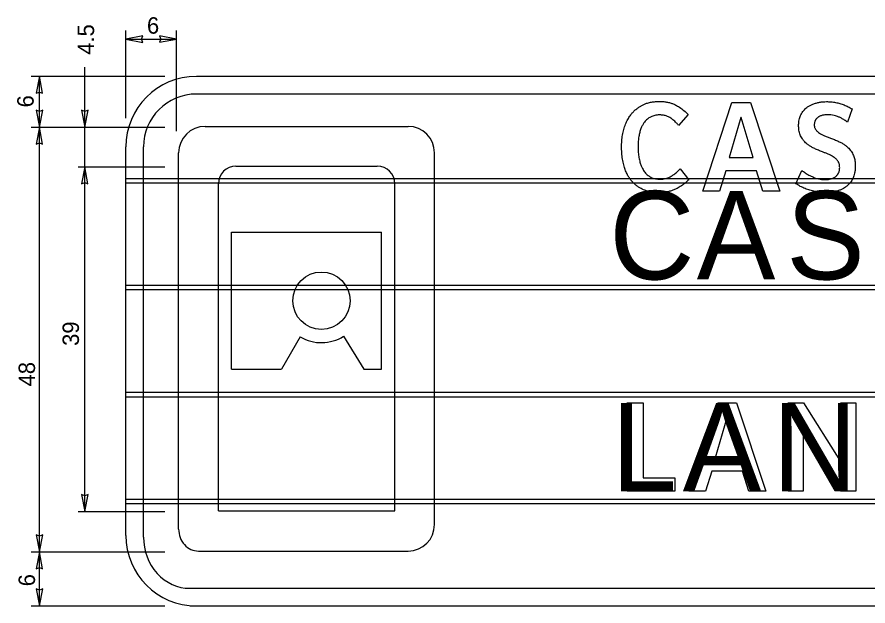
# Model space of a CAD drawing. Extents: x 319706 to 320449, y 1621775 to 1622117.
# Drawn here: x 320308.6 to 320381.2, y 1621854.2 to 1621904.4 of the extents above; entities that cross this region are included whole.
import ezdxf

# ---------------------------------------------------------------- set-up
doc = ezdxf.new("R2010")
doc.units = 0
for name, color, linetype in [('1', 7, 'Continuous'), ('52', 7, 'Continuous'), ('GSBWFill', 7, 'Continuous'), ('GSColorFill', 7, 'Continuous'), ('GSOutline', 7, 'Continuous'), ('SignPanel', 7, 'Continuous')]:
    doc.layers.add(name, color=color, linetype=linetype)

msp = doc.modelspace()

# ---------------------------------------------------------------- linework, layer by layer
at = {"layer": '1'}
for p, q in [((320317.921, 1621895.788), (320317.921, 1621903.248)), ((320322.25, 1621894.663), (320322.25, 1621903.248)), ((320317.921, 1621902.519), (320322.25, 1621902.519)), ((320314.417, 1621895.01), (320314.417, 1621900.114)), ((320309.855, 1621899.343), (320321.239, 1621899.343)), ((320310.552, 1621895.01), (320310.552, 1621899.343)), ((320309.855, 1621895.01), (320321.239, 1621895.01)), ((320310.552, 1621858.786), (320310.552, 1621895.01)), ((320314.417, 1621891.622), (320314.417, 1621895.01)), ((320313.858, 1621891.622), (320321.239, 1621891.622)), ((320314.417, 1621862.212), (320314.417, 1621891.622)), ((320313.858, 1621862.212), (320321.239, 1621862.212)), ((320309.855, 1621858.786), (320321.239, 1621858.786)), ((320310.552, 1621854.168), (320310.552, 1621858.786)), ((320309.855, 1621854.168), (320321.239, 1621854.168))]:
    msp.add_line(p, q, dxfattribs=at)
at = {"layer": '52'}
for p, q in [((320319.371, 1621902.789), (320317.921, 1621902.519)), ((320317.921, 1621902.519), (320319.371, 1621902.239)), ((320319.261, 1621902.519), (320319.371, 1621902.789)), ((320319.371, 1621902.239), (320319.261, 1621902.519)), ((320322.25, 1621902.519), (320320.8, 1621902.799)), ((320320.8, 1621902.799), (320320.91, 1621902.519)), ((320320.91, 1621902.519), (320320.8, 1621902.249)), ((320320.8, 1621902.249), (320322.25, 1621902.519)), ((320310.552, 1621899.343), (320310.272, 1621897.893)), ((320310.822, 1621897.893), (320310.552, 1621899.343)), ((320310.272, 1621897.893), (320310.552, 1621898.003)), ((320310.552, 1621898.003), (320310.822, 1621897.893)), ((320310.552, 1621896.35), (320310.282, 1621896.46)), ((320310.282, 1621896.46), (320310.552, 1621895.01)), ((320310.552, 1621895.01), (320310.832, 1621896.46)), ((320310.832, 1621896.46), (320310.552, 1621896.35)), ((320314.417, 1621896.35), (320314.147, 1621896.46)), ((320314.147, 1621896.46), (320314.417, 1621895.01)), ((320314.417, 1621895.01), (320314.697, 1621896.46)), ((320314.697, 1621896.46), (320314.417, 1621896.35)), ((320310.552, 1621895.01), (320310.272, 1621893.56)), ((320310.822, 1621893.56), (320310.552, 1621895.01)), ((320310.272, 1621893.56), (320310.552, 1621893.67)), ((320310.552, 1621893.67), (320310.822, 1621893.56)), ((320314.417, 1621891.622), (320314.137, 1621890.172)), ((320314.687, 1621890.172), (320314.417, 1621891.622)), ((320314.137, 1621890.172), (320314.417, 1621890.282)), ((320314.417, 1621890.282), (320314.687, 1621890.172)), ((320314.417, 1621863.552), (320314.147, 1621863.662)), ((320314.147, 1621863.662), (320314.417, 1621862.212)), ((320314.417, 1621862.212), (320314.697, 1621863.662)), ((320314.697, 1621863.662), (320314.417, 1621863.552)), ((320310.552, 1621860.126), (320310.282, 1621860.236)), ((320310.282, 1621860.236), (320310.552, 1621858.786)), ((320310.552, 1621858.786), (320310.832, 1621860.236)), ((320310.832, 1621860.236), (320310.552, 1621860.126)), ((320310.552, 1621858.786), (320310.272, 1621857.336)), ((320310.822, 1621857.336), (320310.552, 1621858.786)), ((320310.272, 1621857.336), (320310.552, 1621857.446)), ((320310.552, 1621857.446), (320310.822, 1621857.336)), ((320310.552, 1621855.508), (320310.282, 1621855.618)), ((320310.282, 1621855.618), (320310.552, 1621854.168)), ((320310.552, 1621854.168), (320310.832, 1621855.618)), ((320310.832, 1621855.618), (320310.552, 1621855.508))]:
    msp.add_line(p, q, dxfattribs=at)
at = {"layer": 'GSOutline'}
for points in [[(320372.274, 1621889.554), (320371.724, 1621891.274), (320369.121, 1621891.274), (320368.571, 1621889.554), (320367.157, 1621889.554), (320369.625, 1621897.102), (320371.213, 1621897.102), (320373.733, 1621889.554), (320372.274, 1621889.554)], [(320379.889, 1621896.575), (320379.49, 1621895.438)], [(320365.893, 1621896.095), (320365.088, 1621895.162)], [(320370.437, 1621895.821), (320370.4, 1621895.823), (320369.392, 1621892.409), (320371.446, 1621892.409), (320370.437, 1621895.821)], [(320365.225, 1621891.465), (320365.947, 1621890.525)], [(320375.093, 1621890.183), (320375.605, 1621891.312)], [(320360.7, 1621863.954), (320360.7, 1621871.484), (320362.054, 1621871.484), (320362.054, 1621865.107), (320364.753, 1621865.107), (320364.753, 1621863.954), (320360.7, 1621863.954)], [(320371.082, 1621863.954), (320370.532, 1621865.674), (320367.929, 1621865.674), (320367.379, 1621863.954), (320365.965, 1621863.954), (320368.433, 1621871.502), (320370.02, 1621871.502), (320372.541, 1621863.954), (320371.082, 1621863.954)], [(320378.919, 1621863.954), (320375.735, 1621868.999), (320375.717, 1621868.999), (320375.717, 1621863.954), (320374.427, 1621863.954), (320374.427, 1621871.484), (320375.735, 1621871.484), (320378.9, 1621866.491), (320378.917, 1621866.491), (320378.919, 1621871.484), (320380.218, 1621871.484), (320380.218, 1621863.954), (320378.919, 1621863.954)], [(320369.245, 1621870.221), (320369.208, 1621870.223), (320368.199, 1621866.809), (320370.254, 1621866.809), (320369.245, 1621870.221)]]:
    msp.add_lwpolyline(points, dxfattribs=at)
for points in [[(320360.22, 1621893.333), (320360.223, 1621893.462), (320360.229, 1621893.84), (320360.295, 1621894.338), (320360.407, 1621894.815), (320360.548, 1621895.261), (320360.745, 1621895.677), (320360.963, 1621896.004), (320361.133, 1621896.22), (320361.321, 1621896.419), (320361.574, 1621896.632), (320361.806, 1621896.784), (320362.003, 1621896.892), (320362.213, 1621896.991), (320362.497, 1621897.09), (320362.862, 1621897.167), (320363.186, 1621897.199), (320363.386, 1621897.202), (320363.455, 1621897.203)], [(320363.455, 1621897.203), (320363.516, 1621897.202), (320363.693, 1621897.2), (320363.981, 1621897.171), (320364.312, 1621897.103), (320364.572, 1621897.016), (320364.819, 1621896.907), (320365.166, 1621896.717), (320365.544, 1621896.435), (320365.802, 1621896.184), (320365.893, 1621896.095)], [(320375.326, 1621895.143), (320375.327, 1621895.188), (320375.328, 1621895.316), (320375.349, 1621895.524), (320375.398, 1621895.757), (320375.461, 1621895.937), (320375.524, 1621896.07), (320375.593, 1621896.194), (320375.69, 1621896.34), (320375.825, 1621896.5), (320375.951, 1621896.618), (320376.087, 1621896.725), (320376.292, 1621896.861), (320376.55, 1621896.984), (320376.825, 1621897.071), (320377.114, 1621897.138), (320377.412, 1621897.179), (320377.637, 1621897.183), (320377.713, 1621897.185)], [(320377.713, 1621897.185), (320377.813, 1621897.183), (320378.105, 1621897.177), (320378.489, 1621897.122), (320378.855, 1621897.026), (320379.209, 1621896.905), (320379.556, 1621896.757), (320379.805, 1621896.621), (320379.889, 1621896.575)], [(320363.486, 1621896.05), (320363.448, 1621896.05), (320363.337, 1621896.048), (320363.157, 1621896.029), (320362.952, 1621895.983), (320362.793, 1621895.925), (320362.674, 1621895.867), (320362.561, 1621895.802), (320362.428, 1621895.707), (320362.282, 1621895.572), (320362.173, 1621895.443), (320362.094, 1621895.331), (320361.956, 1621895.111), (320361.835, 1621894.823), (320361.742, 1621894.473), (320361.673, 1621894.115), (320361.634, 1621893.732), (320361.631, 1621893.436), (320361.629, 1621893.333)], [(320365.088, 1621895.162), (320365.027, 1621895.231), (320364.909, 1621895.364), (320364.754, 1621895.517), (320364.601, 1621895.651), (320364.477, 1621895.744), (320364.348, 1621895.825), (320364.219, 1621895.896), (320364.084, 1621895.952), (320363.945, 1621895.995), (320363.798, 1621896.028), (320363.645, 1621896.047), (320363.527, 1621896.049), (320363.486, 1621896.05)], [(320377.813, 1621896.059), (320377.737, 1621896.057), (320377.625, 1621896.055), (320377.479, 1621896.037), (320377.374, 1621896.019), (320377.242, 1621895.988), (320377.133, 1621895.945), (320377.048, 1621895.899), (320377.008, 1621895.875), (320376.957, 1621895.84), (320376.897, 1621895.79), (320376.834, 1621895.723), (320376.788, 1621895.66), (320376.755, 1621895.607), (320376.725, 1621895.549), (320376.696, 1621895.47), (320376.672, 1621895.368), (320376.663, 1621895.276), (320376.662, 1621895.219), (320376.662, 1621895.199)], [(320379.49, 1621895.438), (320379.426, 1621895.484), (320379.238, 1621895.618), (320378.974, 1621895.77), (320378.739, 1621895.88), (320378.57, 1621895.946), (320378.355, 1621896.009), (320378.089, 1621896.053), (320377.894, 1621896.057), (320377.813, 1621896.059)], [(320377.466, 1621892.854), (320377.342, 1621892.903), (320377.09, 1621893.004), (320376.778, 1621893.136), (320376.47, 1621893.283), (320376.239, 1621893.426), (320376.052, 1621893.57), (320375.926, 1621893.679), (320375.784, 1621893.823), (320375.64, 1621894.012), (320375.536, 1621894.19), (320375.458, 1621894.351), (320375.396, 1621894.529), (320375.348, 1621894.761), (320375.328, 1621894.969), (320375.327, 1621895.099), (320375.326, 1621895.143)], [(320376.662, 1621895.199), (320376.662, 1621895.181), (320376.663, 1621895.127), (320376.676, 1621895.039), (320376.706, 1621894.939), (320376.744, 1621894.863), (320376.782, 1621894.806), (320376.858, 1621894.707), (320376.966, 1621894.605), (320377.106, 1621894.507), (320377.289, 1621894.395), (320377.536, 1621894.282), (320377.844, 1621894.163), (320378.027, 1621894.09), (320378.121, 1621894.052)], [(320378.121, 1621894.052), (320378.242, 1621894.005), (320378.487, 1621893.908), (320378.788, 1621893.772), (320379.083, 1621893.618), (320379.303, 1621893.47), (320379.481, 1621893.323), (320379.6, 1621893.21), (320379.735, 1621893.061), (320379.871, 1621892.866), (320379.969, 1621892.684), (320380.042, 1621892.519), (320380.099, 1621892.337), (320380.155, 1621892.058), (320380.162, 1621891.849), (320380.166, 1621891.718)], [(320363.449, 1621889.426), (320363.312, 1621889.429), (320363.11, 1621889.434), (320362.786, 1621889.473), (320362.484, 1621889.532), (320362.2, 1621889.625), (320361.989, 1621889.718), (320361.791, 1621889.82), (320361.559, 1621889.966), (320361.306, 1621890.172), (320361.118, 1621890.367), (320360.983, 1621890.536), (320360.855, 1621890.716), (320360.681, 1621891.006), (320360.519, 1621891.378), (320360.399, 1621891.778), (320360.291, 1621892.274), (320360.229, 1621892.796), (320360.222, 1621893.196), (320360.22, 1621893.333)], [(320361.629, 1621893.333), (320361.633, 1621893.161), (320361.642, 1621892.822), (320361.699, 1621892.404), (320361.785, 1621892.007), (320361.886, 1621891.709), (320362.004, 1621891.468), (320362.097, 1621891.309), (320362.201, 1621891.162), (320362.345, 1621891.004), (320362.48, 1621890.888), (320362.595, 1621890.806), (320362.719, 1621890.731), (320362.89, 1621890.656), (320363.116, 1621890.597), (320363.318, 1621890.573), (320363.444, 1621890.571), (320363.487, 1621890.57)], [(320378.83, 1621891.581), (320378.83, 1621891.602), (320378.829, 1621891.665), (320378.817, 1621891.767), (320378.79, 1621891.883), (320378.756, 1621891.973), (320378.721, 1621892.04), (320378.683, 1621892.105), (320378.618, 1621892.198), (320378.527, 1621892.296), (320378.423, 1621892.385), (320378.291, 1621892.481), (320378.145, 1621892.568), (320377.947, 1621892.665), (320377.733, 1621892.756), (320377.557, 1621892.821), (320377.466, 1621892.854)], [(320377.572, 1621890.533), (320377.612, 1621890.534), (320377.73, 1621890.536), (320377.886, 1621890.554), (320378.038, 1621890.585), (320378.183, 1621890.624), (320378.319, 1621890.682), (320378.428, 1621890.748), (320378.5, 1621890.801), (320378.566, 1621890.86), (320378.638, 1621890.94), (320378.689, 1621891.015), (320378.725, 1621891.08), (320378.759, 1621891.149), (320378.792, 1621891.246), (320378.824, 1621891.396), (320378.828, 1621891.51), (320378.83, 1621891.581)], [(320380.166, 1621891.718), (320380.164, 1621891.622), (320380.158, 1621891.391), (320380.11, 1621891.081), (320380.036, 1621890.836), (320379.975, 1621890.687), (320379.909, 1621890.548), (320379.814, 1621890.385), (320379.681, 1621890.207), (320379.554, 1621890.074), (320379.444, 1621889.978), (320379.328, 1621889.888), (320379.173, 1621889.787), (320378.936, 1621889.667), (320378.677, 1621889.577), (320378.32, 1621889.494), (320377.983, 1621889.451), (320377.726, 1621889.446), (320377.637, 1621889.445)], [(320363.487, 1621890.57), (320363.529, 1621890.571), (320363.653, 1621890.573), (320363.854, 1621890.596), (320364.084, 1621890.651), (320364.265, 1621890.721), (320364.439, 1621890.81), (320364.689, 1621890.967), (320364.964, 1621891.195), (320365.156, 1621891.394), (320365.225, 1621891.465)], [(320375.605, 1621891.312), (320375.679, 1621891.259), (320375.897, 1621891.101), (320376.207, 1621890.918), (320376.487, 1621890.777), (320376.691, 1621890.688), (320376.902, 1621890.617), (320377.164, 1621890.56), (320377.389, 1621890.536), (320377.526, 1621890.534), (320377.572, 1621890.533)], [(320365.947, 1621890.525), (320365.86, 1621890.44), (320365.606, 1621890.195), (320365.223, 1621889.922), (320364.868, 1621889.733), (320364.607, 1621889.621), (320364.334, 1621889.531), (320363.991, 1621889.46), (320363.693, 1621889.43), (320363.511, 1621889.427), (320363.449, 1621889.426)], [(320377.637, 1621889.445), (320377.517, 1621889.447), (320377.17, 1621889.453), (320376.717, 1621889.513), (320376.29, 1621889.621), (320375.878, 1621889.761), (320375.476, 1621889.947), (320375.191, 1621890.123), (320375.093, 1621890.183)]]:
    msp.add_open_spline(points, degree=3, dxfattribs=at)
at = {"layer": 'SignPanel'}
for p, q in [((320323.944, 1621899.343), (320420.317, 1621899.343)), ((320323.944, 1621897.838), (320420.317, 1621897.838)), ((320324.685, 1621895.073), (320342.002, 1621895.073)), ((320317.921, 1621860.191), (320317.921, 1621893.319)), ((320319.427, 1621860.033), (320319.427, 1621893.319)), ((320322.425, 1621860.719), (320322.425, 1621892.816)), ((320344.259, 1621861.109), (320344.259, 1621892.816)), ((320327.319, 1621891.685), (320339.366, 1621891.685)), ((320317.921, 1621890.636), (320426.341, 1621890.636)), ((320317.921, 1621890.26), (320426.341, 1621890.26)), ((320325.813, 1621862.275), (320325.813, 1621890.179)), ((320340.872, 1621862.275), (320340.872, 1621890.179)), ((320326.944, 1621874.369), (320326.944, 1621886.039)), ((320326.944, 1621886.039), (320339.742, 1621886.039)), ((320339.742, 1621874.379), (320339.742, 1621886.039)), ((320317.921, 1621881.527), (320426.341, 1621881.527)), ((320317.921, 1621881.151), (320426.341, 1621881.151)), ((320332.806, 1621877.116), (320331.202, 1621874.369)), ((320336.5, 1621877.167), (320338.237, 1621874.379)), ((320326.944, 1621874.369), (320331.202, 1621874.369)), ((320338.237, 1621874.379), (320339.742, 1621874.379)), ((320317.921, 1621872.417), (320426.341, 1621872.417)), ((320317.921, 1621872.011), (320426.341, 1621872.011)), ((320317.921, 1621863.277), (320426.341, 1621863.277)), ((320317.921, 1621862.902), (320426.341, 1621862.902)), ((320325.813, 1621862.275), (320340.872, 1621862.275)), ((320324.119, 1621858.849), (320342.002, 1621858.849)), ((320323.38, 1621855.673), (320420.317, 1621855.673)), ((320323.411, 1621854.168), (320420.317, 1621854.168))]:
    msp.add_line(p, q, dxfattribs=at)
msp.add_circle((320334.61, 1621880.205), 2.447, dxfattribs=at)
for centre, radius, start, end in [((320323.944, 1621893.319), 6.023, 90, 180), ((320323.944, 1621893.319), 4.517, 90, 180), ((320324.684, 1621892.816), 2.259, 90, 180), ((320342.001, 1621892.816), 2.259, 0, 90), ((320327.319, 1621890.181), 1.506, 90, 180), ((320339.366, 1621890.181), 1.506, 0, 90), ((320334.61, 1621880.205), 3.576, 239.72059, 301.90487), ((320342.001, 1621861.109), 2.259, 270, 360), ((320323.944, 1621860.191), 6.023, 180, 270)]:
    msp.add_arc(centre, radius, start, end, dxfattribs=at)
for centre, major_axis in [((320324.119, 1621860.719), (0, 1.868)), ((320323.379, 1621860.033), (0, 4.36))]:
    msp.add_ellipse(centre, major_axis=major_axis, ratio=0.906668, start_param=1.570796, end_param=3.141593, dxfattribs=at)

# ---------------------------------------------------------------- texts
at = {"layer": '1'}
msp.add_text('6', height=1.4, dxfattribs=at).set_placement((320319.723, 1621902.981))
for s, p in [('4.5', (320315.212, 1621901.181)), ('6', (320310.055, 1621896.693)), ('39', (320313.92, 1621876.353)), ('48', (320310.169, 1621872.896)), ('6', (320310.169, 1621855.845))]:
    msp.add_text(s, height=1.4, rotation=90, dxfattribs=at).set_placement(p)
at = {"layer": 'GSBWFill'}
for s, p in [('C', (320359.168, 1621882.025)), ('A', (320366.63, 1621882.025)), ('S', (320374.265, 1621882.025)), ('L', (320359.346, 1621863.954)), ('A', (320365.438, 1621863.954)), ('N', (320373.073, 1621863.954))]:
    msp.add_text(s, height=7.53, dxfattribs=at).set_placement(p)
at = {"layer": 'GSColorFill'}
for s, p in [('C', (320359.168, 1621882.025)), ('A', (320366.63, 1621882.025)), ('S', (320374.265, 1621882.025)), ('L', (320359.346, 1621863.954)), ('A', (320365.438, 1621863.954)), ('N', (320373.073, 1621863.954))]:
    msp.add_text(s, height=7.53, dxfattribs=at).set_placement(p)

doc.saveas('drawing.dxf')
